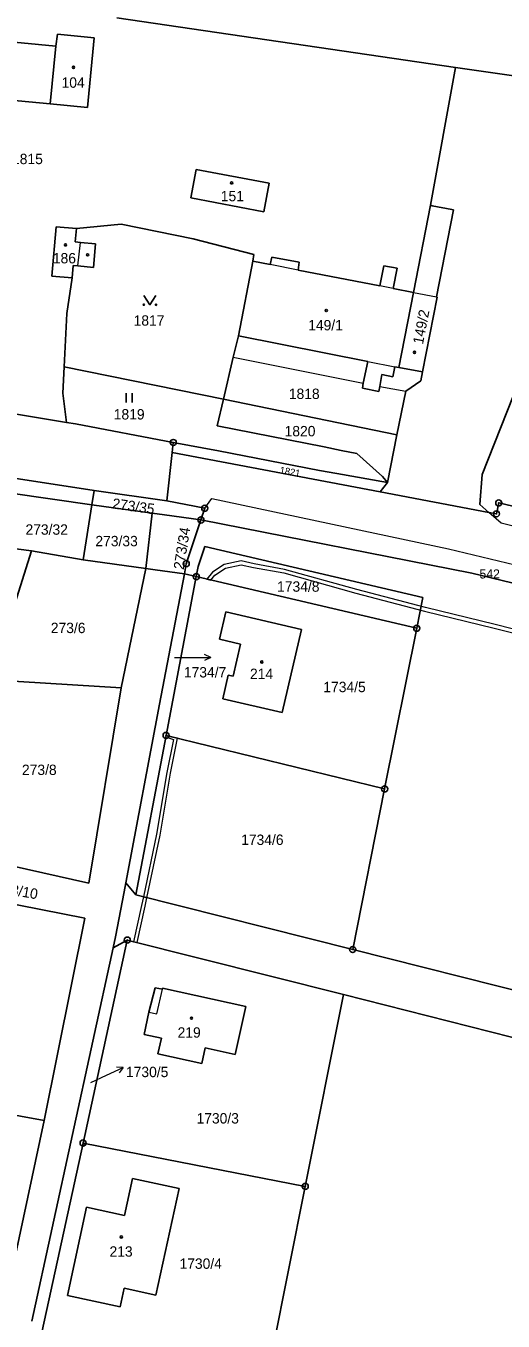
# Model space of a CAD drawing. Extents: x -601131 to -597152, y -1058536 to -1055911.
# Drawn here: x -599290.5 to -599212.3, y -1057278.4 to -1057066.1 of the extents above; entities that cross this region are included whole.
import ezdxf
from ezdxf.enums import TextEntityAlignment as Align

# ---------------------------------------------------------------- set-up
doc = ezdxf.new("R2010")
doc.units = 0
doc.header["$LTSCALE"] = 0.68
for name, color, linetype, lineweight in [('1', 7, 'Continuous', 25), ('13', 7, 'Continuous', 13), ('3', 7, 'Continuous', 25), ('4', 7, 'Continuous', 13), ('5', 7, 'Continuous', 25), ('7', 7, 'Continuous', 13), ('8', 7, 'Continuous', 25)]:
    doc.layers.add(name, color=color, linetype=linetype, lineweight=lineweight)
doc.layers.add('2', color=7, linetype='Continuous')

msp = doc.modelspace()

# ---------------------------------------------------------------- linework, layer by layer
at = {"layer": '1'}
for p, q in [((-599220.11, -1057072.92), (-599275.6, -1057064.81)), ((-599285.62, -1057069.45), (-599307.96, -1057067.36)), ((-599285.62, -1057069.45), (-599285.37, -1057067.49)), ((-599285.37, -1057067.49), (-599279.32, -1057068.08)), ((-599279.32, -1057068.08), (-599280.43, -1057079.48)), ((-599286.54, -1057078.9), (-599285.62, -1057069.45)), ((-599224.19, -1057095.53), (-599220.11, -1057072.92)), ((-599220.11, -1057072.92), (-599206.53, -1057074.91)), ((-599308.83, -1057076.76), (-599286.54, -1057078.9)), ((-599280.43, -1057079.48), (-599286.54, -1057078.9)), ((-599263.48, -1057094.3), (-599262.6, -1057089.64)), ((-599262.6, -1057089.64), (-599250.66, -1057091.92)), ((-599250.66, -1057091.92), (-599251.53, -1057096.57)), ((-599251.53, -1057096.57), (-599263.48, -1057094.3)), ((-599224.19, -1057095.53), (-599226.99, -1057109.81)), ((-599223.9, -1057095.6), (-599224.19, -1057095.53)), ((-599220.71, -1057096.19), (-599223.9, -1057095.6)), ((-599223.22, -1057110.54), (-599220.4, -1057096.27)), ((-599220.4, -1057096.27), (-599220.71, -1057096.19)), ((-599286.3, -1057107.12), (-599285.58, -1057099.05)), ((-599285.58, -1057099.05), (-599282.26, -1057099.35)), ((-599282.26, -1057099.35), (-599282.45, -1057101.53)), ((-599282.26, -1057099.35), (-599274.9, -1057098.61)), ((-599274.9, -1057098.61), (-599263.08, -1057101.02)), ((-599282.45, -1057101.53), (-599281.6, -1057101.61)), ((-599281.6, -1057101.61), (-599279.11, -1057101.84)), ((-599279.11, -1057101.84), (-599279.47, -1057105.71)), ((-599263.08, -1057101.02), (-599253.18, -1057103.61)), ((-599253.33, -1057104.69), (-599255.67, -1057116.89)), ((-599253.18, -1057103.61), (-599253.33, -1057104.69)), ((-599250.46, -1057105.25), (-599253.33, -1057104.69)), ((-599250.2, -1057104), (-599250.46, -1057105.25)), ((-599245.7, -1057104.84), (-599250.2, -1057104)), ((-599245.91, -1057106.13), (-599245.7, -1057104.84)), ((-599282.79, -1057105.4), (-599282.96, -1057107.4)), ((-599282.04, -1057105.47), (-599282.79, -1057105.4)), ((-599279.47, -1057105.71), (-599282.04, -1057105.47)), ((-599232.49, -1057108.74), (-599245.91, -1057106.13)), ((-599231.83, -1057105.44), (-599232.49, -1057108.74)), ((-599229.64, -1057105.83), (-599231.83, -1057105.44)), ((-599230.33, -1057109.16), (-599229.64, -1057105.83)), ((-599282.96, -1057107.4), (-599286.3, -1057107.12)), ((-599283.8, -1057113.25), (-599282.96, -1057107.4)), ((-599226.99, -1057109.81), (-599230.33, -1057109.16)), ((-599226.99, -1057109.81), (-599229.38, -1057122.11)), ((-599225.47, -1057122.84), (-599223.09, -1057110.57)), ((-599223.09, -1057110.57), (-599223.22, -1057110.54)), ((-599284.25, -1057121.97), (-599283.8, -1057113.25)), ((-599255.67, -1057116.89), (-599256.52, -1057120.4)), ((-599255.67, -1057116.89), (-599234.47, -1057121.1)), ((-599256.52, -1057120.4), (-599258.14, -1057127.32)), ((-599234.47, -1057121.1), (-599235.21, -1057124.65)), ((-599284.25, -1057121.97), (-599284.47, -1057126.31)), ((-599258.14, -1057127.32), (-599284.25, -1057121.97)), ((-599232.49, -1057125.24), (-599232.18, -1057123.24)), ((-599232.18, -1057123.24), (-599230.38, -1057123.62)), ((-599230.38, -1057123.62), (-599230.05, -1057121.98)), ((-599230.05, -1057121.98), (-599229.38, -1057122.11)), ((-599229.38, -1057122.11), (-599225.47, -1057122.84)), ((-599225.75, -1057124.3), (-599225.47, -1057122.84)), ((-599235.21, -1057124.65), (-599235.36, -1057125.48)), ((-599235.36, -1057125.48), (-599232.67, -1057126.01)), ((-599232.67, -1057126.01), (-599232.49, -1057125.24)), ((-599229.7, -1057133.15), (-599228.25, -1057125.98)), ((-599228.25, -1057125.98), (-599225.75, -1057124.3)), ((-599284.47, -1057126.31), (-599283.88, -1057131.11)), ((-599259.15, -1057131.65), (-599258.14, -1057127.32)), ((-599258.14, -1057127.32), (-599229.7, -1057133.15)), ((-599210.61, -1057126.79), (-599215.7, -1057139.66)), ((-599283.88, -1057131.11), (-599293.72, -1057129.47)), ((-599283.88, -1057131.11), (-599282.39, -1057131.36)), ((-599282.39, -1057131.36), (-599266.37, -1057134.39)), ((-599241.64, -1057135.11), (-599259.15, -1057131.65)), ((-599279.34, -1057142.28), (-599341.7, -1057132.63)), ((-599266.37, -1057134.39), (-599266.55, -1057136.03)), ((-599266.37, -1057134.39), (-599258.94, -1057135.77)), ((-599229.7, -1057133.15), (-599231.26, -1057140.95)), ((-599267.42, -1057143.94), (-599266.55, -1057136.03)), ((-599266.55, -1057136.03), (-599232.45, -1057142.49)), ((-599258.94, -1057135.77), (-599242.36, -1057138.96)), ((-599238.85, -1057135.69), (-599241.64, -1057135.11)), ((-599236.29, -1057136.18), (-599238.85, -1057135.69)), ((-599232.03, -1057139.94), (-599236.29, -1057136.18)), ((-599242.36, -1057138.96), (-599239.57, -1057139.45)), ((-599239.57, -1057139.45), (-599231.26, -1057140.95)), ((-599232.45, -1057142.49), (-599231.26, -1057140.95)), ((-599231.26, -1057140.95), (-599232.03, -1057139.94)), ((-599215.7, -1057139.66), (-599216.11, -1057144.55)), ((-599279.71, -1057144.58), (-599293, -1057142.72)), ((-599279.71, -1057144.58), (-599279.34, -1057142.28)), ((-599279.34, -1057142.28), (-599267.42, -1057143.94)), ((-599214.64, -1057145.84), (-599232.45, -1057142.49)), ((-599281.16, -1057153.6), (-599279.71, -1057144.58)), ((-599269.81, -1057145.97), (-599279.71, -1057144.58)), ((-599261.2, -1057145.17), (-599267.42, -1057143.94)), ((-599261.84, -1057147.09), (-599261.2, -1057145.17)), ((-599216.11, -1057144.55), (-599214.64, -1057145.84)), ((-599213.36, -1057146.08), (-599212.99, -1057144.29)), ((-599212.99, -1057144.29), (-599203.71, -1057146.48)), ((-599270.88, -1057155.03), (-599269.81, -1057145.97)), ((-599269.81, -1057145.97), (-599267.81, -1057146.25)), ((-599267.81, -1057146.25), (-599261.84, -1057147.09)), ((-599264.24, -1057154.25), (-599261.84, -1057147.09)), ((-599261.84, -1057147.09), (-599217.43, -1057155.81)), ((-599214.64, -1057145.84), (-599213.36, -1057146.08)), ((-599289.64, -1057152.13), (-599294.32, -1057151.54)), ((-599261.18, -1057151.43), (-599262.29, -1057154.73)), ((-599225.43, -1057159.79), (-599261.18, -1057151.43)), ((-599289.64, -1057152.13), (-599296.29, -1057173.26)), ((-599289.64, -1057152.13), (-599281.16, -1057153.6)), ((-599281.16, -1057153.6), (-599270.88, -1057155.03)), ((-599270.88, -1057155.03), (-599274.91, -1057174.6)), ((-599270.88, -1057155.03), (-599269.31, -1057155.25)), ((-599269.31, -1057155.25), (-599264.55, -1057155.91)), ((-599264.55, -1057155.91), (-599264.24, -1057154.25)), ((-599262.29, -1057154.73), (-599262.6, -1057156.37)), ((-599217.43, -1057155.81), (-599169.22, -1057167.54)), ((-599264.55, -1057155.91), (-599268.6, -1057177.25)), ((-599267.55, -1057182.39), (-599262.6, -1057156.37)), ((-599264.55, -1057155.91), (-599262.6, -1057156.37)), ((-599262.6, -1057156.37), (-599226.44, -1057164.83)), ((-599226.44, -1057164.83), (-599225.43, -1057159.79)), ((-599257.73, -1057162.14), (-599258.78, -1057166.63)), ((-599245.34, -1057165.03), (-599257.73, -1057162.14)), ((-599245.34, -1057165.03), (-599248.53, -1057178.66)), ((-599226.44, -1057164.83), (-599231.7, -1057191.15)), ((-599258.78, -1057166.63), (-599255.32, -1057167.46)), ((-599255.32, -1057167.46), (-599256.56, -1057172.67)), ((-599257.34, -1057172.5), (-599258.25, -1057176.37)), ((-599256.56, -1057172.67), (-599257.34, -1057172.5)), ((-599296.29, -1057173.26), (-599274.91, -1057174.6)), ((-599274.91, -1057174.6), (-599280.22, -1057206.58)), ((-599248.53, -1057178.66), (-599258.25, -1057176.37)), ((-599274.17, -1057206.56), (-599268.6, -1057177.25)), ((-599272.51, -1057208.52), (-599267.55, -1057182.39)), ((-599231.7, -1057191.15), (-599267.55, -1057182.39)), ((-599231.7, -1057191.15), (-599236.94, -1057217.47)), ((-599304.24, -1057201.25), (-599280.22, -1057206.58)), ((-599274.44, -1057208), (-599274.17, -1057206.56)), ((-599272.51, -1057208.52), (-599274.17, -1057206.56)), ((-599280.87, -1057212.34), (-599303.41, -1057207.92)), ((-599275.85, -1057215.41), (-599274.44, -1057208)), ((-599272.51, -1057208.52), (-599236.94, -1057217.47)), ((-599287.53, -1057245.47), (-599280.87, -1057212.34)), ((-599289.57, -1057278.37), (-599276.24, -1057217.2)), ((-599281.16, -1057249.18), (-599273.92, -1057215.93)), ((-599276.24, -1057217.2), (-599275.85, -1057215.41)), ((-599276.24, -1057217.2), (-599273.92, -1057215.93)), ((-599273.92, -1057215.93), (-599238.44, -1057224.85)), ((-599236.94, -1057217.47), (-599165.88, -1057235.34)), ((-599269.35, -1057223.73), (-599270.38, -1057227.75)), ((-599269.35, -1057223.73), (-599268.16, -1057223.99)), ((-599268.16, -1057223.99), (-599268.12, -1057223.8)), ((-599254.49, -1057226.79), (-599268.12, -1057223.8)), ((-599244.72, -1057256.29), (-599238.44, -1057224.85)), ((-599145.12, -1057248.56), (-599238.44, -1057224.85)), ((-599270.38, -1057227.75), (-599271.16, -1057231.38)), ((-599254.49, -1057226.79), (-599256.24, -1057234.68)), ((-599271.16, -1057231.38), (-599268.32, -1057232.02)), ((-599268.32, -1057232.02), (-599268.88, -1057234.56)), ((-599261.16, -1057233.59), (-599261.71, -1057236.14)), ((-599256.24, -1057234.68), (-599261.16, -1057233.59)), ((-599268.88, -1057234.56), (-599261.71, -1057236.14)), ((-599309.65, -1057241.5), (-599287.53, -1057245.47)), ((-599295.06, -1057280.63), (-599287.53, -1057245.47)), ((-599287.86, -1057279.94), (-599281.16, -1057249.18)), ((-599244.72, -1057256.29), (-599281.16, -1057249.18)), ((-599274.35, -1057261.04), (-599273.04, -1057254.97)), ((-599273.04, -1057254.97), (-599265.42, -1057256.62)), ((-599265.42, -1057256.62), (-599269.23, -1057274.1)), ((-599251, -1057287.69), (-599244.72, -1057256.29)), ((-599283.74, -1057274.14), (-599280.6, -1057259.69)), ((-599280.6, -1057259.69), (-599274.35, -1057261.04)), ((-599275.08, -1057276), (-599283.74, -1057274.14)), ((-599274.44, -1057272.96), (-599275.08, -1057276)), ((-599269.23, -1057274.1), (-599274.44, -1057272.96))]:
    msp.add_line(p, q, dxfattribs=at)
at = {"layer": '13'}
msp.add_lwpolyline([(-599200.27, -1057167.58), (-599213.59, -1057164.24), (-599225.02, -1057161.43), (-599236.25, -1057158.48), (-599248.12, -1057155.19), (-599253.09, -1057154.29), (-599255.26, -1057153.81), (-599258.03, -1057154.41), (-599259.96, -1057155.65), (-599260.87, -1057156.78), (-599260.22, -1057156.93), (-599259.56, -1057156.11), (-599257.79, -1057154.97), (-599255.26, -1057154.43), (-599253.21, -1057154.87), (-599248.26, -1057155.77), (-599236.41, -1057159.06), (-599225.16, -1057162.01), (-599213.73, -1057164.82), (-599200.43, -1057168.16)], dxfattribs=at)
for points in [[(-599267.43, -1057188.49), (-599269.1, -1057198.59), (-599271.27, -1057208.83), (-599270.68, -1057208.98), (-599268.52, -1057198.71), (-599266.83, -1057188.59), (-599265.69, -1057182.85), (-599267.3, -1057182.45), (-599267.32, -1057182.57), (-599267.09, -1057182.61), (-599267.13, -1057182.81), (-599266.34, -1057183.04)], [(-599270.68, -1057208.98), (-599271.27, -1057208.83), (-599271.56, -1057210.25), (-599272.9, -1057216.19), (-599272.31, -1057216.33), (-599270.98, -1057210.37)], [(-599280.84, -1057249.24), (-599281.04, -1057249.2), (-599281.07, -1057249.32), (-599280.87, -1057249.37)]]:
    msp.add_lwpolyline(points, close=True, dxfattribs=at)
at = {"layer": '3'}
for p, q in [((-599274.111, -1057127.83), (-599274.111, -1057126.33)), ((-599273.11, -1057127.83), (-599273.11, -1057126.33))]:
    msp.add_line(p, q, dxfattribs=at)
msp.add_lwpolyline([(-599271.2, -1057110.319), (-599270.2, -1057111.82), (-599269.2, -1057110.319)], dxfattribs=at)
for centre in [(-599271.2, -1057111.8195), (-599269.2, -1057111.8195)]:
    msp.add_circle(centre, 0.1, dxfattribs=at)
at = {"layer": '4'}
for p, q in [((-599282.04, -1057105.47), (-599281.6, -1057101.61)), ((-599245.91, -1057106.13), (-599250.46, -1057105.25)), ((-599230.33, -1057109.16), (-599232.49, -1057108.74)), ((-599226.99, -1057109.81), (-599223.22, -1057110.54)), ((-599256.52, -1057120.4), (-599235.21, -1057124.65)), ((-599234.47, -1057121.1), (-599230.05, -1057121.98)), ((-599232.49, -1057125.24), (-599228.25, -1057125.98)), ((-599261.2, -1057145.17), (-599260.07, -1057143.58)), ((-599260.07, -1057143.58), (-599221.22, -1057151.81)), ((-599212.59, -1057147.63), (-599214.64, -1057145.84)), ((-599159.66, -1057160.88), (-599212.59, -1057147.63)), ((-599221.22, -1057151.81), (-599194.02, -1057158.4)), ((-599269.05, -1057228.03), (-599268.16, -1057223.99)), ((-599270.38, -1057227.75), (-599269.05, -1057228.03))]:
    msp.add_line(p, q, dxfattribs=at)
at = {"layer": '5'}
for centre in [(-599282.7268, -1057072.9092), (-599256.7968, -1057091.8592), (-599284.0368, -1057102.0192), (-599280.4068, -1057103.6492), (-599241.2768, -1057112.7592), (-599226.8168, -1057119.6192), (-599251.8568, -1057170.3592), (-599263.3868, -1057228.7192), (-599274.8868, -1057264.5692)]:
    msp.add_circle(centre, 0.175, dxfattribs=at)
at = {"layer": '7'}
for p, q in [((-599260.219, -1057169.63), (-599261.22, -1057169.129)), ((-599274.57, -1057236.792), (-599275.689, -1057236.761))]:
    msp.add_line(p, q, dxfattribs=at)
for points in [[(-599266.16, -1057169.63), (-599263.22, -1057169.63), (-599260.219, -1057169.63), (-599261.22, -1057170.131)], [(-599279.87, -1057239.25), (-599277.29, -1057238.06), (-599274.57, -1057236.792), (-599275.266, -1057237.669)]]:
    msp.add_lwpolyline(points, dxfattribs=at)
at = {"layer": '8'}
for centre, radius in [((-599266.37, -1057134.3899), 0.5), ((-599266.37, -1057134.3899), 0.0303), ((-599261.2, -1057145.1699), 0.5), ((-599261.2, -1057145.1699), 0.0303), ((-599212.99, -1057144.2899), 0.5), ((-599212.99, -1057144.2899), 0.0303), ((-599261.84, -1057147.0899), 0.5), ((-599261.84, -1057147.0899), 0.0303), ((-599213.36, -1057146.0799), 0.5), ((-599213.36, -1057146.0799), 0.0303), ((-599264.24, -1057154.2499), 0.5), ((-599264.24, -1057154.2499), 0.0303), ((-599262.6, -1057156.3699), 0.5), ((-599262.6, -1057156.3699), 0.0303), ((-599226.44, -1057164.8299), 0.5), ((-599226.44, -1057164.8299), 0.0303), ((-599267.55, -1057182.3899), 0.5), ((-599267.55, -1057182.3899), 0.0303), ((-599231.7, -1057191.1499), 0.5), ((-599231.7, -1057191.1499), 0.0303), ((-599273.92, -1057215.9299), 0.5), ((-599273.92, -1057215.9299), 0.0303), ((-599236.94, -1057217.4699), 0.5), ((-599236.94, -1057217.4699), 0.0303), ((-599281.16, -1057249.1799), 0.5), ((-599281.16, -1057249.1799), 0.0303), ((-599244.72, -1057256.2899), 0.5), ((-599244.72, -1057256.2899), 0.0303)]:
    msp.add_circle(centre, radius, dxfattribs=at)

# ---------------------------------------------------------------- texts
at = {"layer": '2'}
for s, p in [('104', (-599282.789, -1057076.262)), ('1815', (-599290.28, -1057088.782)), ('151', (-599256.679, -1057094.862)), ('186', (-599284.219, -1057105.042)), ('1817', (-599270.34, -1057115.252)), ('149/1', (-599241.4, -1057116.022)), ('1818', (-599244.89, -1057127.262)), ('1819', (-599273.6, -1057130.622)), ('1820', (-599245.58, -1057133.382)), ('1734/7', (-599261.15, -1057172.895)), ('214', (-599251.889, -1057173.145)), ('1734/5', (-599238.28, -1057175.304)), ('1734/6', (-599251.76, -1057200.334)), ('219', (-599263.759, -1057231.915)), ('1730/5', (-599270.65, -1057238.385)), ('1730/3', (-599259.08, -1057245.985)), ('213', (-599274.929, -1057267.804)), ('1730/4', (-599261.87, -1057269.795))]:
    msp.add_text(s, height=1.7, dxfattribs=at).set_placement(p, align=Align.CENTER)
for s, height, rotation, p in [('149/2', 1.7, 79, (-599224.8837, -1057115.6012)), ('1821', 1.139, 350, (-599247.3079, -1057139.7452))]:
    msp.add_text(s, height=height, rotation=rotation, dxfattribs=at).set_placement(p, align=Align.CENTER)
for s, rotation, p in [('273/35', 352, (-599276.449, -1057145.19)), ('273/34', 81, (-599264.66, -1057155.306)), ('273/10', 350, (-599295.593, -1057208.048))]:
    msp.add_text(s, height=1.7, rotation=rotation, dxfattribs=at).set_placement(p)
for s, p in [('273/32', (-599290.6, -1057149.505)), ('273/33', (-599279.14, -1057151.395)), ('1734/8', (-599249.34, -1057158.844)), ('273/6', (-599286.45, -1057165.625)), ('273/8', (-599291.18, -1057188.875))]:
    msp.add_text(s, height=1.7, dxfattribs=at).set_placement(p)
at = {"layer": '8'}
msp.add_text('542', height=1.5, dxfattribs=at).set_placement((-599212.809, -1057156.677), align=Align.RIGHT)

doc.saveas('drawing.dxf')
